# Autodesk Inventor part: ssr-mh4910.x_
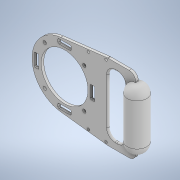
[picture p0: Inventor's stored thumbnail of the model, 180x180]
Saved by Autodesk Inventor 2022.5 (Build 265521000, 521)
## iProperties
Created: 2022-03
Part Number: ssr-mh4910.x_
Material: 一般
Document SubType Name: Modeling
Designer: ImaoCorp
Density: 1 g/cm^3
Appearance: 既定
Sending System: SOLIDWORKS 2020-2020296
MC: AMD64
MC_MODEL: Intel64 Family 6 Model 60 Stepping 3, GenuineIntel
OS: Windows_NT
FRU: Parasolid Version 31.1, build 290,  3- 9-2020
FORMAT: text
GUISE: transmit
KEY: ssr-mh4910
FILE: ssr-mh4910.x_t
DATE: Mon Mar  7 17:35:03 2022
Author: ImaoCorp
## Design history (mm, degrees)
feature "Base1"
node "ソリッド1"
